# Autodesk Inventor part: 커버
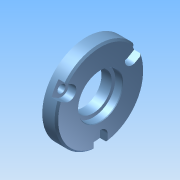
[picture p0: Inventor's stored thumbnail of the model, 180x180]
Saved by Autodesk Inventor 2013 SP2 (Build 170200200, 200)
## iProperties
Created: 2025-10
Part Number: 커버
Material: Generic
Document SubType Name: Modeling
Designer: 601
Density: 1 g/cm^3
Author: 601
변환 표준: STEP AP214IS
전처리기: Build: 200, Release: 2013 SP2 Update 6 - Date: Thu 07/17/2014
전송 단위: 밀리미터
불확실성: 0.01
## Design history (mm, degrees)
node "커버1"
node "솔리드1"
node "기준1"
